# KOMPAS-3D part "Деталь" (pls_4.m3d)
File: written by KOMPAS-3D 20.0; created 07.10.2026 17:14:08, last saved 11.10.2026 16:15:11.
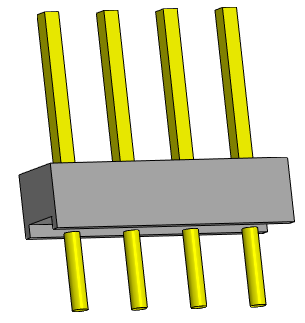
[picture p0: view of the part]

Document properties: Полное имя файла: D:\myProjects\Progect_esp32\box_compas\pls_4.m3d

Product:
- Part/product: Деталь
    Масса: 0.000521406

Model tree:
1. Эскиз:1
2. Элемент выдавливания:1
     Расстояние 1 = 2.5
3. Эскиз:2  (with: Элемент выдавливания:1)
4. Элемент выдавливания:2
     Расстояние 1 = 6
5. Массив по сетке:1  (with: Элемент выдавливания:2, Эскиз:2)  (4 pattern instances)
     Шаг 1 = 2.54; Угол раствора = 90
6. Эскиз:3  (with: Элемент выдавливания:1)
7. Элемент выдавливания:3
     Расстояние 1 = 3
8. Массив по сетке:2  (with: Элемент выдавливания:3, Эскиз:3)  (4 pattern instances)
     Шаг 1 = 2.54; Угол раствора = 90; Геометрический массив = 128
9. Эскиз:4  (with: Элемент выдавливания:1)
10. Элемент выдавливания:4
     Расстояние 2 = 10.16
11. Элемент выдавливания:5
     Расстояние 1 = 3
